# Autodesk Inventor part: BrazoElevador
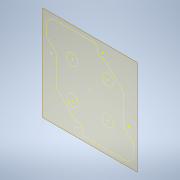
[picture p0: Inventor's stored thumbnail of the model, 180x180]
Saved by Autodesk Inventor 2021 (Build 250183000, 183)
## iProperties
Created: 2021-02
Part Number: BrazoElevador
Material: Genérico
Document SubType Name: Modeling
Designer: ATOUZA
Density: 1 g/cm^3
Appearance: Valor por defecto
Author: ATOUZA
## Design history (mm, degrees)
node "Plano de trabajo1"
sketch "Boceto1"
  geometry: L1 (-16.63, 19)-(2.213, 19) reference; L2 (-19, 10.73)-(-19, 16.63) reference; L3 (-2.213, -19)-(-3.402, -17.812) reference; L4 (-19, 19)-(19, 19); L5 (19, -19.787)-(-19, -19.787); L6 (-19, -19.787)-(-19, 19); L7 (-110.947, -70)-(189.053, -70); L8 (189.053, -70)-(189.053, -170); L9 (189.053, -170)-(-110.947, -170); L10 (-110.947, -170)-(-110.947, -70); L11 (-110.947, -120)-(189.053, -120); L12 (100.5, -18.287)-(135.5, -18.287) reference; L13 (100.5, 16.713)-(100.5, -18.287) reference; L14 (118, -18.287)-(118, 0); L15 (19, 19)-(120.884, 9.961); L16 (19, -19.787)-(120.96, -9.954); L17 (49, 16.338)-(49, -16.894); C1 r 5 at (120, 0); A1 r 120 centre (0, 0) between (120, 0) and (119.583, 9.991); A2 r 10 centre (120, 0) between (118, -9.798) and (119.583, 9.991); 2 further points
  constraints: 24 end point, 6 point on circle, 4 point on line, 3 centre point, 3 midpoint, 3 parallel, 3 tangent, 2 coincident, 2 horizontal, 2 vertical, 1 perpendicular
  dimensions: "d0" = 38 distance of L5.start L5.end; "d3" = 300 distance of L8.end L9.end; "d4" = 100 distance of L7.end L8.end; "d6" = 120 distance from line of L11 point (0, 0); "d7" = 10 diameter of C1; "d8" = 20 diameter of A2
extrude "Extrusión1" new body sketch "Boceto1" distance "d1" = 5; taper "d2" = 0 deg
node "Sólido1"
node "Referencia3"
node "Referencia4"
